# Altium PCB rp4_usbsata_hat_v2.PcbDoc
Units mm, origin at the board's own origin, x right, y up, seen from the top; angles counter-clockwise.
Board outline 100 x 100 mm, 4 copper layers (Top Layer, Int1 (GND), Int2 (PWR), Bottom Layer), stack 1.369 mm thick; 67 components, 71 nets, 344 pads, 194 vias.
Unrouted connection lines stored in the file: 33.
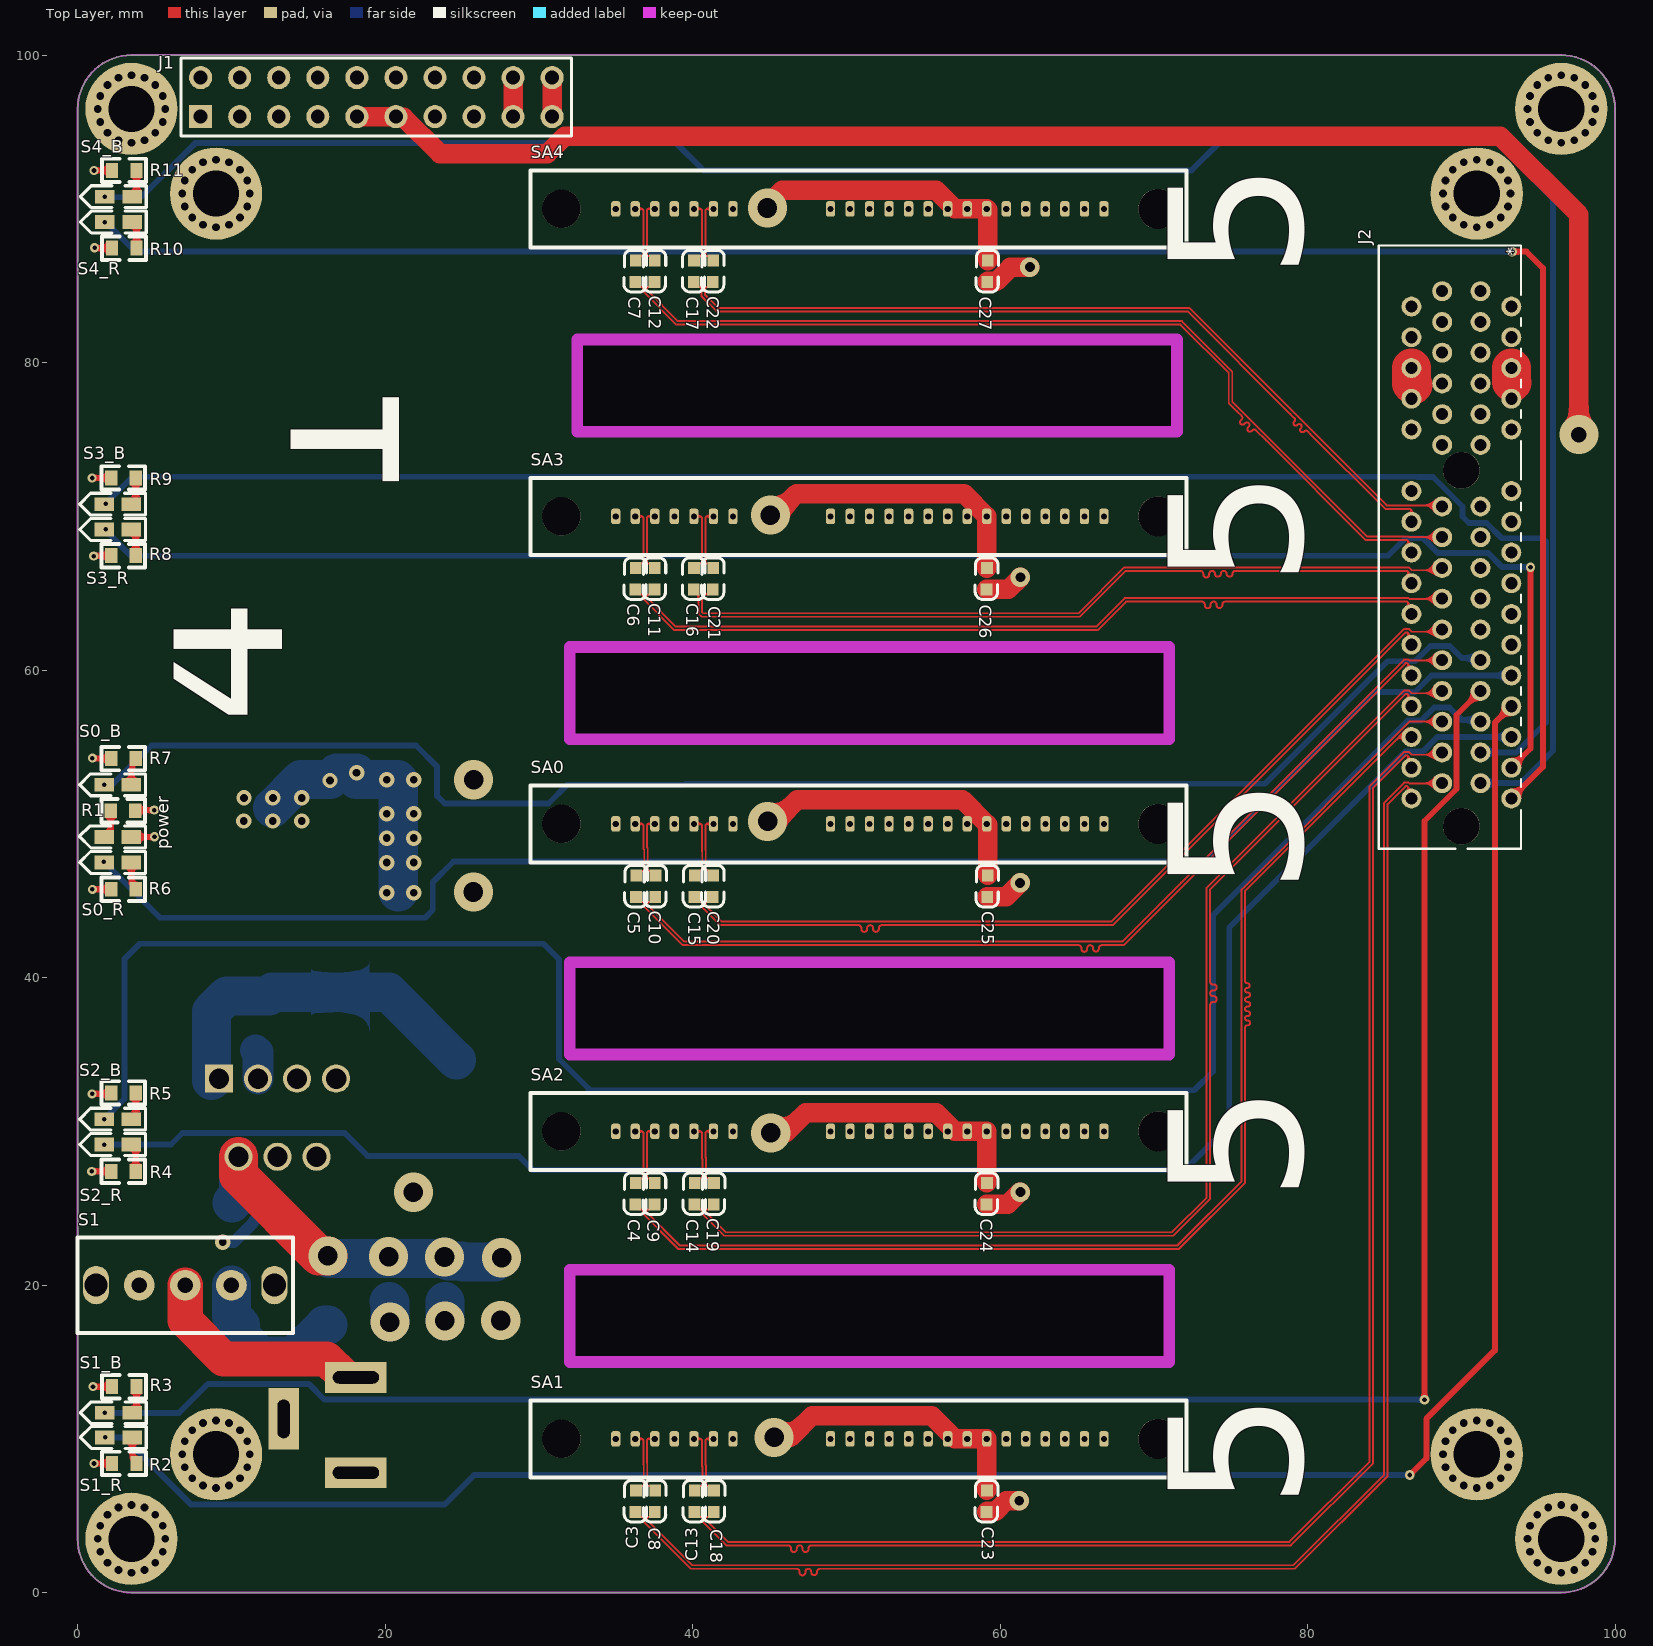
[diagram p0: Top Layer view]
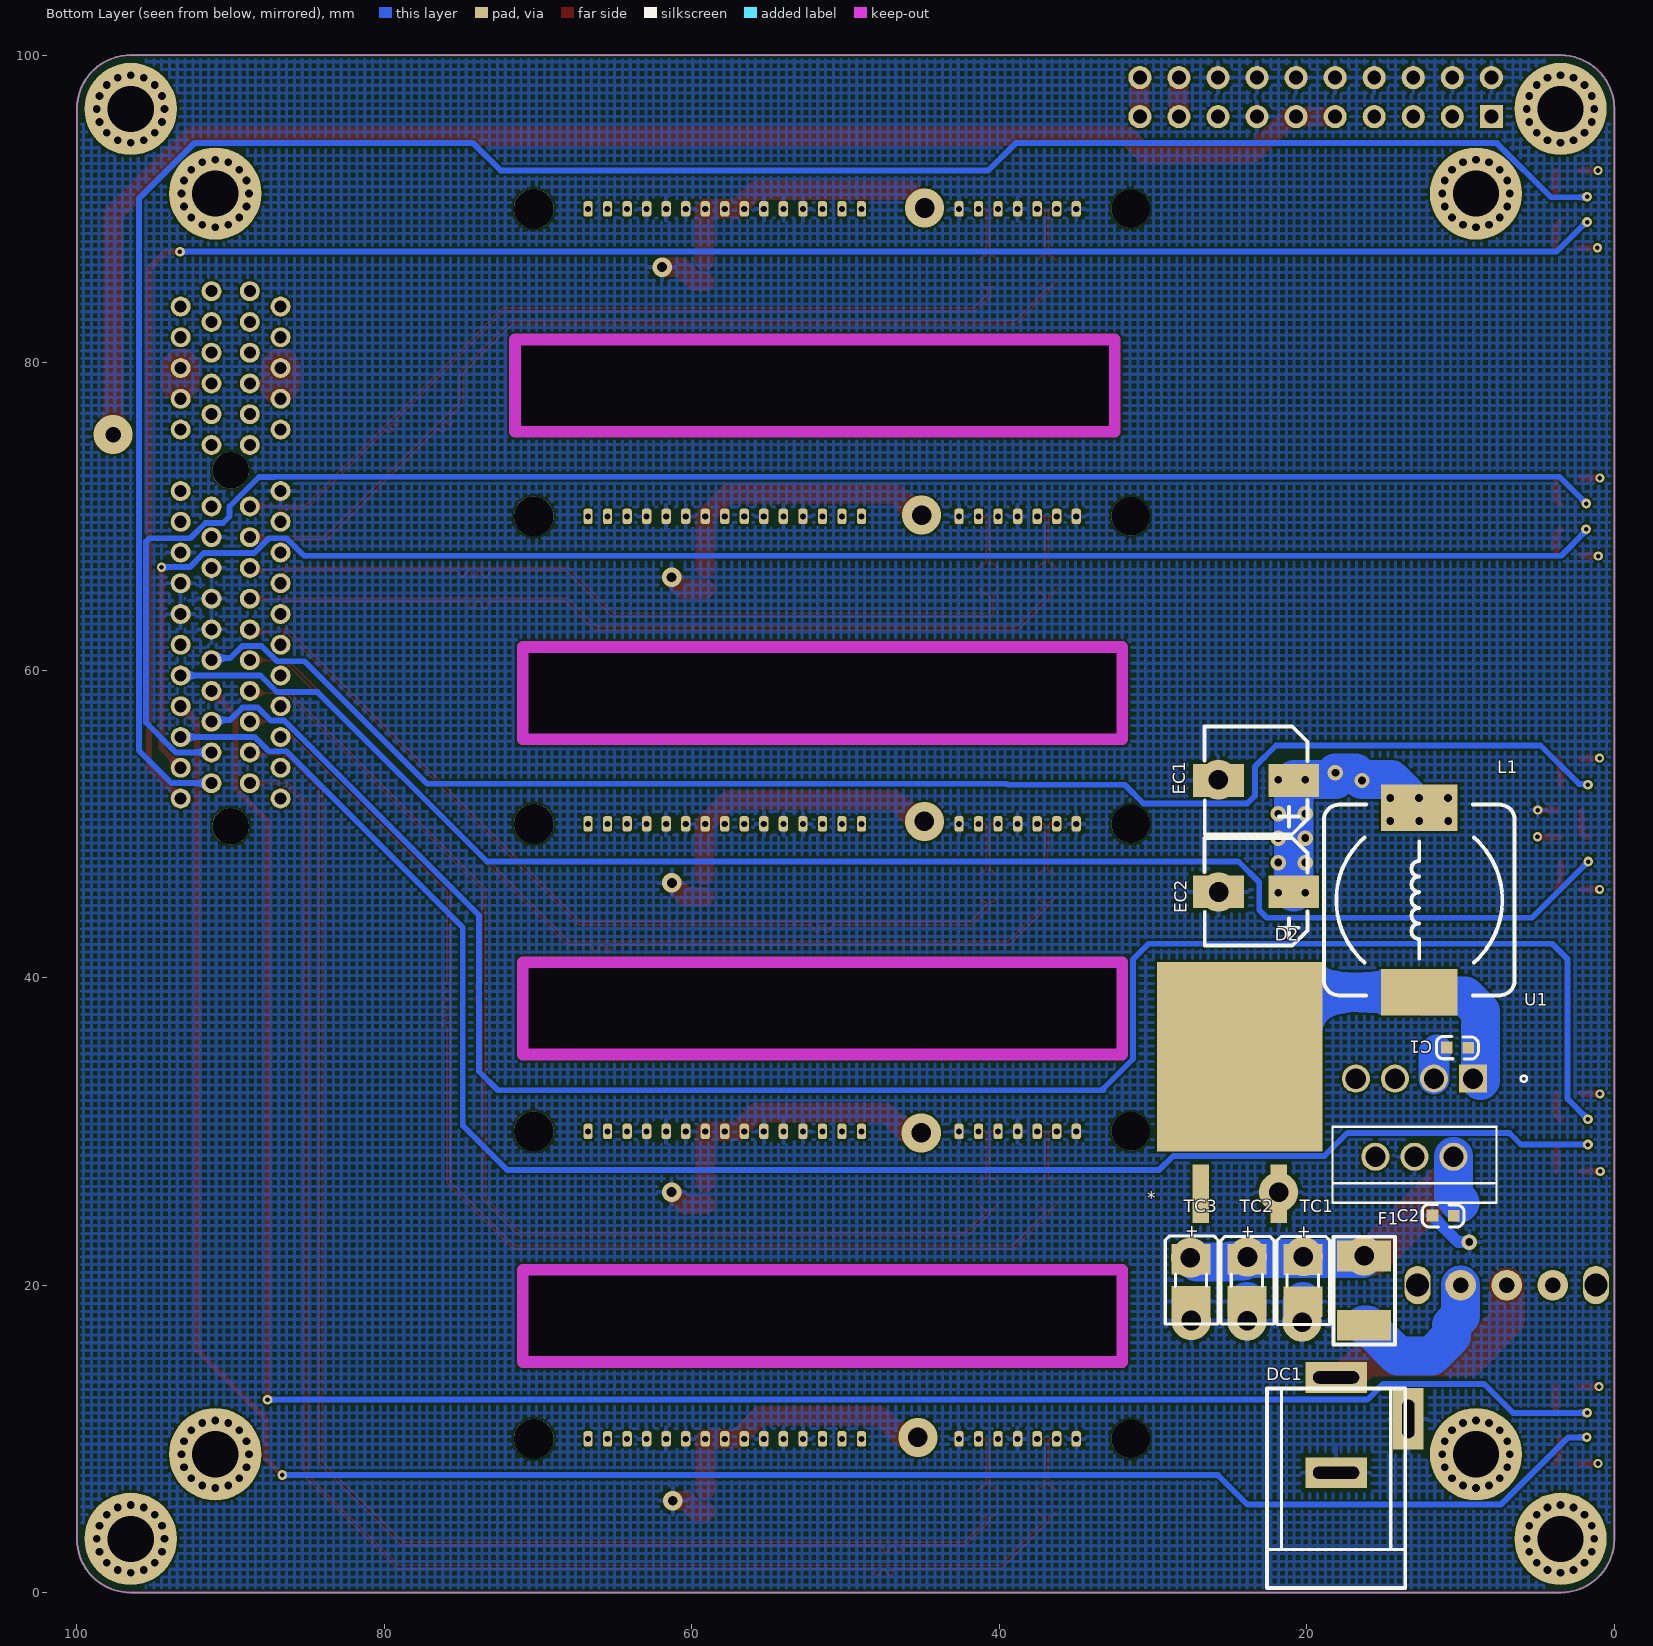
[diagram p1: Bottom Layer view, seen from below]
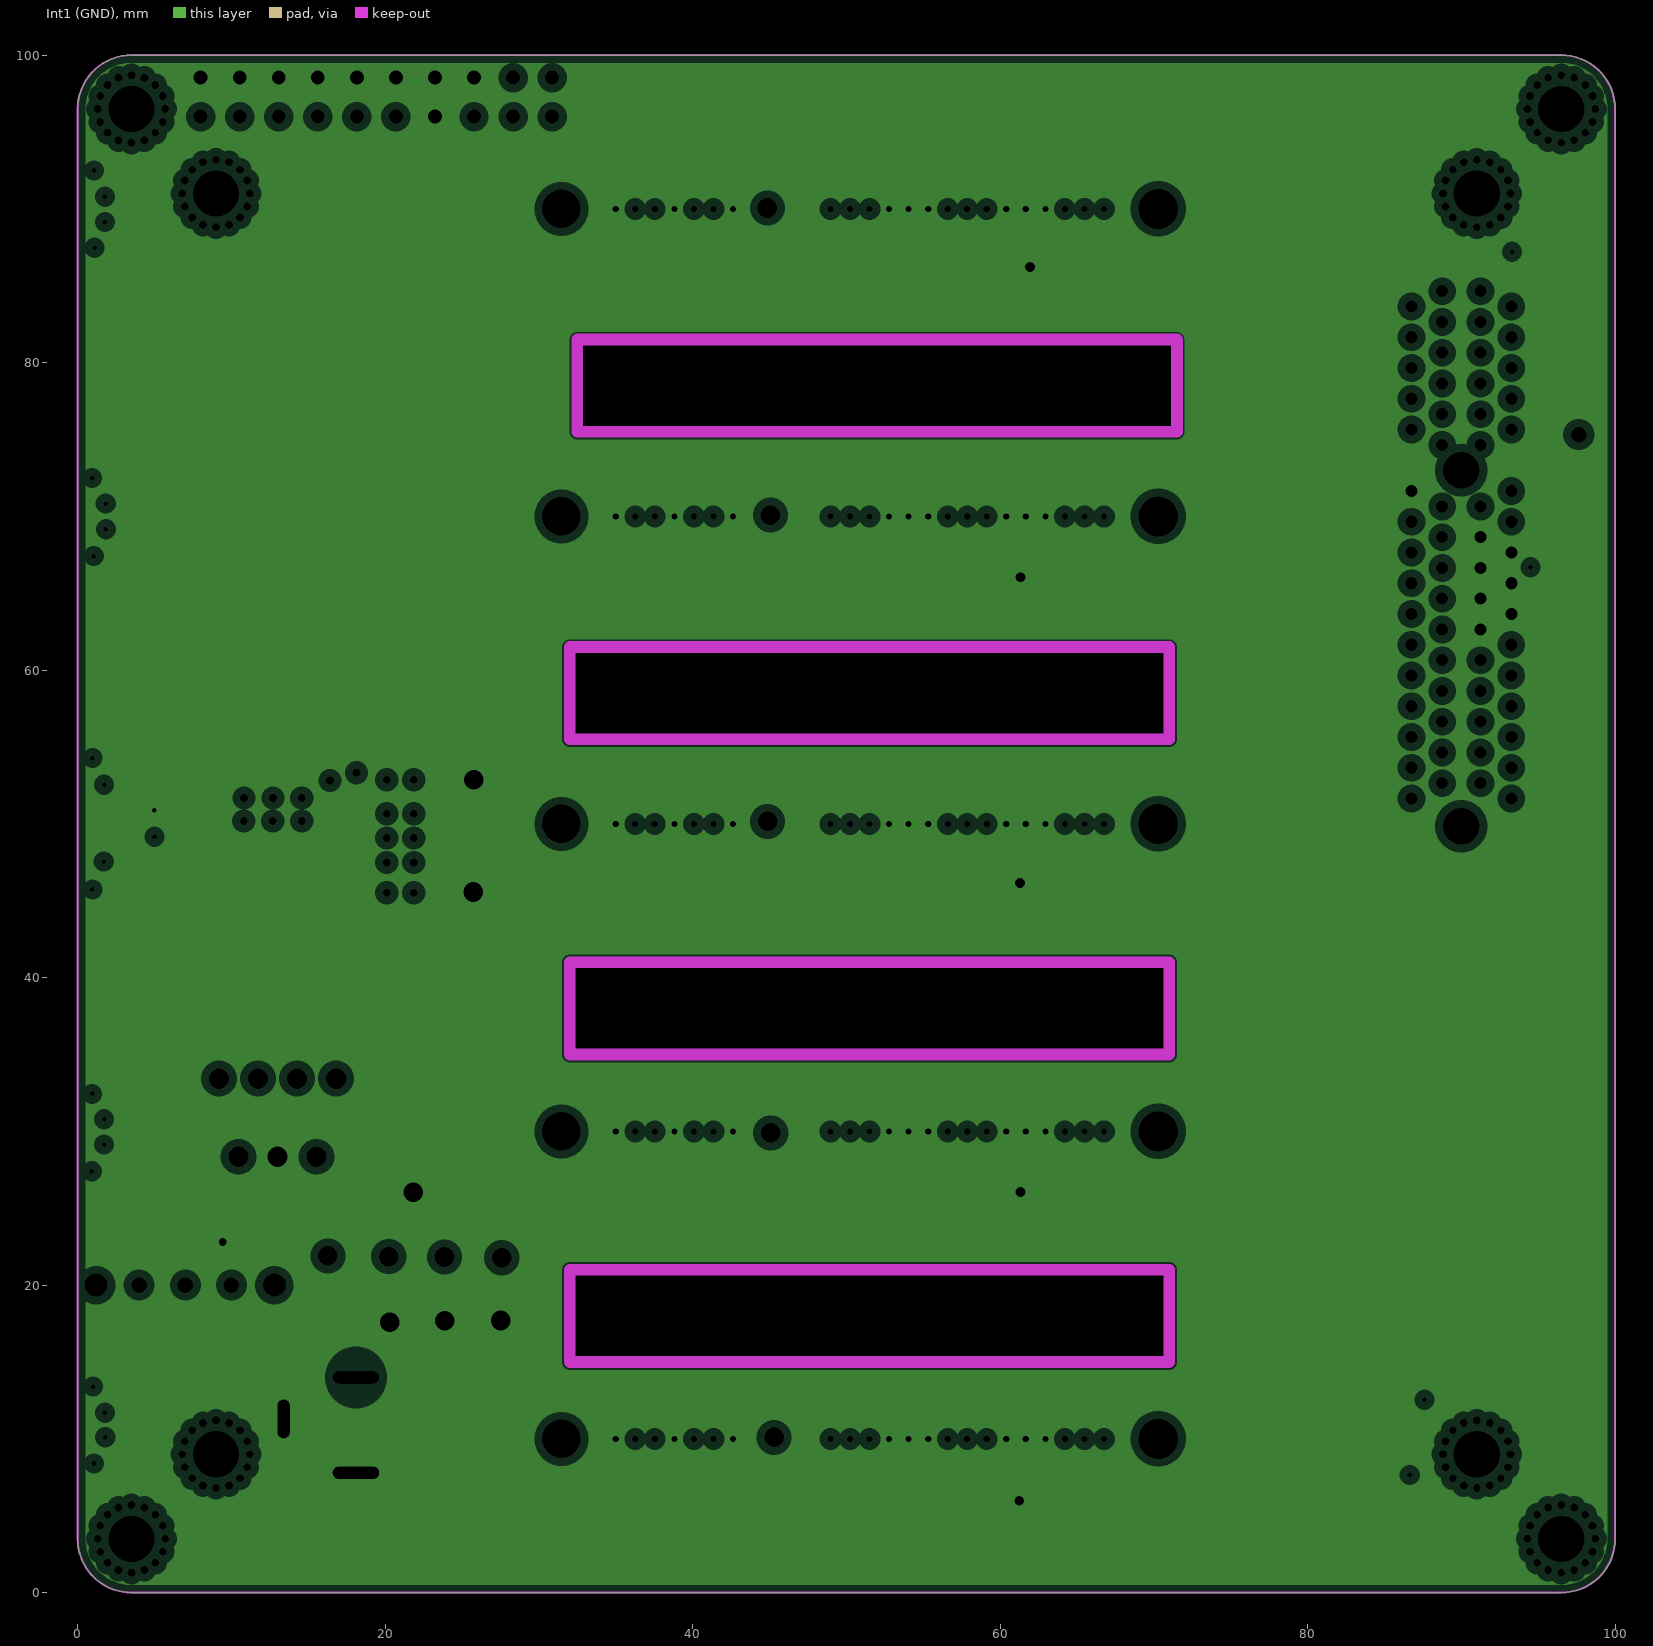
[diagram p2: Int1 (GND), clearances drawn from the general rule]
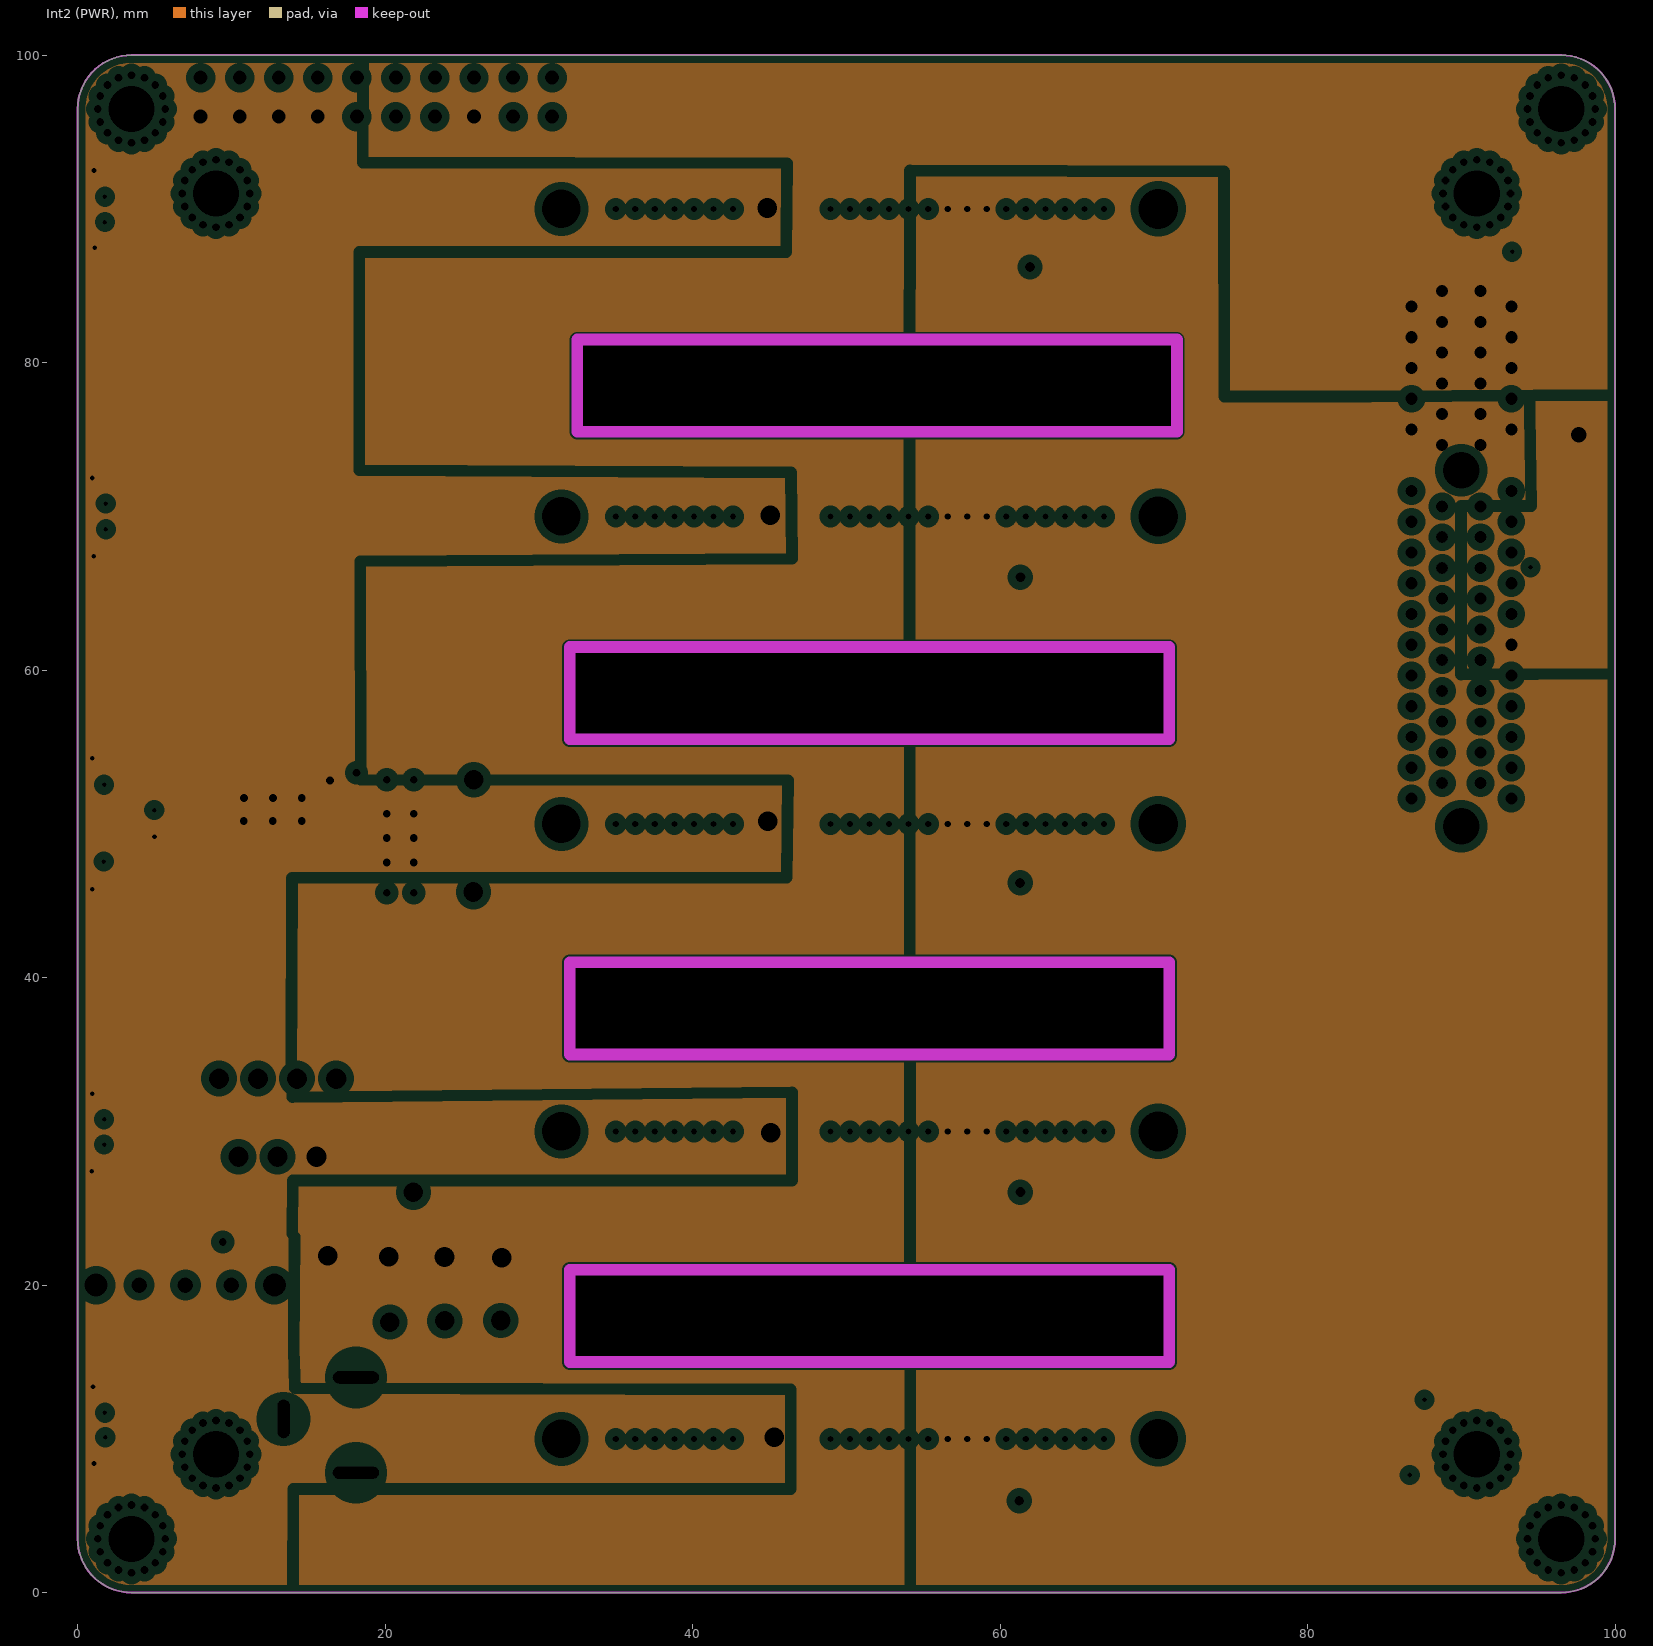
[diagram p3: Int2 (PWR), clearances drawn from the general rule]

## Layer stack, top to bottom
Top Solder: solder mask 0.0254, SM-001, Dk 4
Top Layer: signal copper 0.035
Dielectric 1: prepreg 0.1295, PP-017, Dk 4.3
Dielectric 2: prepreg 0.1295, PP-017, Dk 4.3
Int1 (GND): plane copper 0.035, net GND
Dielectric 3: core 0.7112, Core-039, Dk 4.8
Int2 (PWR): plane copper 0.035, net (Multiple Nets)
Dielectric 4: prepreg 0.1295, PP-017, Dk 4.3
Dielectric 5: prepreg 0.1295, PP-017, Dk 4.3
Bottom Layer: signal copper 0.035
Bottom Solder: solder mask 0.0254, SM-001, Dk 4

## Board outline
0,3.5 0,96.5 cw(c3.5,96.5) 3.5,100 96.5,100 cw(c96.5,96.5) 100,96.5 100,3.5 cw(c96.5,3.5) 96.5,0 3.5,0 cw(c3.5,3.5)
cut-out: 32,55.5 32,61.5 71,61.5 71,55.5
cut-out: 32.5,75.5 71.5,75.5 71.5,81.5 32.5,81.5
cut-out: 32,15 71,15 71,21 32,21
cut-out: 32,35 71,35 71,41 32,41

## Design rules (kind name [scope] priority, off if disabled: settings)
Clearance [All] p1: gap=0.127 ignorepadtopadclearanceinfootprint=FALSE
Clearance Clearance_1 [All] p2: gap=0.089 ignorepadtopadclearanceinfootprint=FALSE
DiffPairsRouting DiffPair_SATA_CDiffPairsRouting [InDifferentialPair ('NewDifferentialPair2') Or InDifferentialPair ('NewDifferentialPair1') Or InDifferentialPair ('NewDifferentialPair5') Or InDifferentialPair ('NewDifferentialPair6') Or InDifferentialPair ('NewDifferentialPair8') Or InDifferentialPair ('NewDifferentialPair9') Or InDifferentialPair ('NewDifferentialPair10') Or InDifferentialPair ('NewDifferentialPair4') Or InDifferentialPair ('NewDifferentialPair3') Or InDifferentialPair ('NewDifferentialPair7')] p1: maxlimit=0.102 minlimit=0.102 mostfreqgap=0.102 toplayer_minwidth=0.126 toplayer_maxwidth=0.126 toplayer_prefwidth=0.126 bottomlayer_minwidth=0.126 bottomlayer_maxwidth=0.126 bottomlayer_prefwidth=0.126 maxuncoupledlength=12.7
DiffPairsRouting DiffPair_SATADiffPairsRouting [InDifferentialPair ('RX1') Or InDifferentialPair ('RX3') Or InDifferentialPair ('TX2') Or InDifferentialPair ('TX3') Or InDifferentialPair ('RX4') Or InDifferentialPair ('TX1') Or InDifferentialPair ('TX4') Or InDifferentialPair ('RX2')] p2: maxlimit=0.102 minlimit=0.102 mostfreqgap=0.102 toplayer_minwidth=0.126 toplayer_maxwidth=0.126 toplayer_prefwidth=0.126 bottomlayer_minwidth=0.126 bottomlayer_maxwidth=0.126 bottomlayer_prefwidth=0.126 maxuncoupledlength=12.7
DiffPairsRouting DiffPair_SATA0DiffPairsRouting [InDifferentialPair ('TX0') Or InDifferentialPair ('RX0')] p3: maxlimit=0.102 minlimit=0.102 mostfreqgap=0.102 toplayer_minwidth=0.126 toplayer_maxwidth=0.126 toplayer_prefwidth=0.126 bottomlayer_minwidth=0.126 bottomlayer_maxwidth=0.126 bottomlayer_prefwidth=0.126 maxuncoupledlength=12.7
DiffPairsRouting [All] p4: maxlimit=0.254 minlimit=0.254 mostfreqgap=0.254 toplayer_minwidth=0.381 toplayer_maxwidth=0.381 toplayer_prefwidth=0.381 bottomlayer_minwidth=0.381 bottomlayer_maxwidth=0.381 bottomlayer_prefwidth=0.381 maxuncoupledlength=12.7
HoleSize [All] p1: absolutevalues=TRUE maxlimit=10 minlimit=0.025 maxpercent=80.000 minpercent=20.000
HoleToHoleClearance [All] p1: gap=0.127 allowstackedmicrovias=TRUE
MatchedLengths DiffPair_SATA_CMatchedLengths [InDifferentialPair ('NewDifferentialPair2') Or InDifferentialPair ('NewDifferentialPair1') Or InDifferentialPair ('NewDifferentialPair5') Or InDifferentialPair ('NewDifferentialPair6') Or InDifferentialPair ('NewDifferentialPair8') Or InDifferentialPair ('NewDifferentialPair9') Or InDifferentialPair ('NewDifferentialPair10') Or InDifferentialPair ('NewDifferentialPair4') Or InDifferentialPair ('NewDifferentialPair3') Or InDifferentialPair ('NewDifferentialPair7')] p1: tolerance=0.076 checknetsindiffpair=TRUE checkdiffpairvsdiffpair=FALSE checkxsignals=FALSE checkothers=FALSE
MatchedLengths DiffPair_SATAMatchedLengths [InDifferentialPair ('RX1') Or InDifferentialPair ('RX3') Or InDifferentialPair ('TX2') Or InDifferentialPair ('TX3') Or InDifferentialPair ('RX4') Or InDifferentialPair ('TX1') Or InDifferentialPair ('TX4') Or InDifferentialPair ('RX2')] p2: tolerance=0.076 checknetsindiffpair=TRUE checkdiffpairvsdiffpair=FALSE checkxsignals=FALSE checkothers=FALSE
MatchedLengths DiffPair_SATA0MatchedLengths [InDifferentialPair ('TX0') Or InDifferentialPair ('RX0')] p3: tolerance=0.076 checknetsindiffpair=TRUE checkdiffpairvsdiffpair=FALSE checkxsignals=FALSE checkothers=FALSE
MinimumSolderMaskSliver [All] p1: minsoldermaskwidth=0.126
PlaneClearance [All] p1: clearance=0.508
PlaneConnect [All] p1: planeconnectstyle=Relief reliefexpansion=0.508 reliefentries=4 reliefconductorwidth=0.254 reliefairgap=0.254
PolygonConnect [All] p1: connectstyle=Relief reliefconductorwidth=0.254 reliefentries=4 polygonreliefangle="90 Angle" airgapwidth=0.254
RoutingVias [All] p1: holewidth=0.3 width=0.6 viastyle="Through Hole" minholewidth=0.3 minwidth=0.6 maxholewidth=5 maxwidth=10
SilkToSilkClearance [All] p1 off: silktosilkclearance=0.254
SilkToSolderMaskClearance [IsPad] p1 off: minsilkscreentomaskgap=0.254 clearancetoexposedcopper=TRUE
SolderMaskExpansion [All] p1: expansion=0.102 istentingtop=FALSE
Width [All] p1: maxlimit=5.08 minlimit=0.254 preferedwidth=0.254
22 further rules are at their usual default settings.

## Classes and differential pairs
differential pair NewDifferentialPair10: +NetC7_1 -NetC12_1
differential pair NewDifferentialPair9: +NetC22_1 -NetC17_1
differential pair NewDifferentialPair8: +NetC21_1 -NetC16_1
differential pair NewDifferentialPair7: +NetC6_1 -NetC11_1
differential pair NewDifferentialPair6: +NetC5_1 -NetC10_1
differential pair NewDifferentialPair5: +NetC20_1 -NetC15_1
differential pair NewDifferentialPair4: +NetC4_1 -NetC9_1
differential pair NewDifferentialPair3: +NetC19_1 -NetC14_1
differential pair NewDifferentialPair2: +NetC18_1 -NetC13_1
differential pair NewDifferentialPair1: +NetC3_1 -NetC8_1
differential pair TX4: +TX4_P -TX4_N
differential pair TX3: +TX3_P -TX3_N
differential pair TX2: +TX2_P -TX2_N
differential pair TX1: +TX1_P -TX1_N
differential pair TX0: +TX0_P -TX0_N
differential pair RX4: +RX4_P -RX4_N
differential pair RX3: +RX3_P -RX3_N
differential pair RX2: +RX2_P -RX2_N
differential pair RX1: +RX1_P -RX1_N
differential pair RX0: +RX0_P -RX0_N

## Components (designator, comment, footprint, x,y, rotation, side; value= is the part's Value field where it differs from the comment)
C1 "0.01uF" 0603C 10.91,35.47 r180 bottom
C2 "0.47uF" 0603C 11.84,24.54 r180 bottom
C3 "10nF" 0603C 36.32,6.65 r270 top
C4 "10nF" 0603C 36.3,26.65 r270 top
C5 "10nF" 0603C 36.35,46.65 r270 top
C6 "10nF" 0603C 36.3,66.65 r270 top
C7 "10nF" 0603C 36.3,86.65 r270 top
C8 "10nF" 0603C 37.57,6.65 r270 top
C9 "10nF" 0603C 37.55,26.65 r270 top
C10 "10nF" 0603C 37.6,46.65 r270 top
C11 "10nF" 0603C 37.55,66.65 r270 top
C12 "10nF" 0603C 37.55,86.65 r270 top
C13 "10nF" 0603C 40.15,6.65 r270 top
C14 "10nF" 0603C 40.15,26.65 r270 top
C15 "10nF" 0603C 40.15,46.65 r270 top
C16 "10nF" 0603C 40.1,66.65 r270 top
C17 "10nF" 0603C 40.1,86.65 r270 top
C18 "10nF" 0603C 41.4,6.65 r270 top
C19 "10nF" 0603C 41.4,26.65 r270 top
C20 "10nF" 0603C 41.35,46.65 r270 top
C21 "10nF" 0603C 41.35,66.65 r270 top
C22 "10nF" 0603C 41.35,86.65 r270 top
C23 "4.7uF" 0603C 59.15,6.65 r270 top
C24 "4.7uF" 0603C 59.15,26.65 r270 top
C25 "4.7uF" 0603C 59.2,46.65 r270 top
C26 "4.7uF" 0603C 59.15,66.65 r270 top
C27 "4.7uF" 0603C 59.2,86.65 r270 top
D2 "VS-6TQ045SPBF" TO-263-2 24.362,30.4 r180 bottom
DC1 "DC_12V" DC-005 18.1,14 r270 bottom
EC1 "180uF/16V" SMD-EC6.3X6.3X10 20.83,52.83 r0 bottom
EC2 "180uF/16V" SMD-EC6.3X6.3X10 20.83,45.58 r0 bottom
F1 "16V 3A" FUSE-1812 16.28,17.397 r90 bottom
J1 "Power" "Pin HDR2X10/2.54mm-S" 8,96 r0 top
J2 "PCIEX4-64P" PCIEX4-64P 90,73 r270 top
L1 "22uH" CDRH124 12.687,45.05 r90 bottom
power "LED" LED-0603G 3.5,49.15 r180 top
R1 "1K" 0603R 3.75,50.85 r180 top
R2 "330" 0603R 2.229,8.4 r0 top
R3 "330" 0603R 2.229,13.4 r0 top
R4 "330" 0603R 2.179,27.4 r0 top
R5 "330" 0603R 2.179,32.5 r0 top
R6 "330" 0603R 2.179,45.75 r0 top
R7 "330" 0603R 2.179,54.25 r0 top
R8 "330" 0603R 2.179,67.45 r0 top
R9 "330" 0603R 2.179,72.5 r0 top
R10 "330" 0603R 2.229,87.45 r0 top
R11 "330" 0603R 2.229,92.5 r0 top
S0_B "LED" LED-0603W 3.5,52.55 r180 top
S0_R "LED" LED-0603W 3.5,47.5 r180 top
S1 "SW_ALL" SS-12D10 10,20 r180 top
S1_B "LED" LED-0603W 3.55,11.7 r180 top
S1_R "LED" LED-0603W 3.55,10.1 r180 top
S2_B "LED" LED-0603W 3.5,30.8 r180 top
S2_R "LED" LED-0603W 3.5,29.15 r180 top
S3_B "LED" LED-0603W 3.5,70.8 r180 top
S3_R "LED" LED-0603W 3.5,69.15 r180 top
S4_B "LED" LED-0603W 3.55,90.8 r180 top
S4_R "LED" LED-0603W 3.55,89.15 r180 top
SA0 "SATA Connector" "SATA Female" 35,50 r0 top
SA1 "SATA Connector" "SATA Female" 35,10 r0 top
SA2 "SATA Connector" "SATA Female" 35,30 r0 top
SA3 "SATA Connector" "SATA Female" 35,70 r0 top
SA4 "SATA Connector" "SATA Female" 35,90 r0 top
TC1 "15uF/16V" TAJ-B/3528 20.16,20.37 r270 bottom
TC2 "15uF/16V" TAJ-B/3528 23.8,20.38 r270 bottom
TC3 "15uF/16V" TAJ-B/3528 27.43,20.39 r270 bottom
U1 "Part Number: LM2678T-5.0/NOPB" TA07Bm_TEX 9.19,33.431 r0 bottom value=Value

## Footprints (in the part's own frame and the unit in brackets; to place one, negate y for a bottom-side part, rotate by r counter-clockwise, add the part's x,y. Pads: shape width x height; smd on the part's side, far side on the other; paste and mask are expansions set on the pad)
0603C [mil]
  rect 30x30 smd: 1(0.21,-0.35) 2(55.21,-1.35)
  silkscreen extent -26,-30 81,28, body extent -1,-15 62,16, height 12
0603R [mm]
  rect 0.8x0.965 smd: 1(0,0) 2(1.6,0)
  silkscreen extent -0.63,-0.76 2.21,0.76, body extent -0.04,-0.41 1.56,0.41, height 0.45
CDRH124 [mm] "12*12*4.5mm（长宽高）"
  rect 3x5 smd: 1(-6,0) 2(6,0)
  silkscreen extent -6.2,-6.2 6.2,6.2, body extent -5.87,-6.03 6.13,5.97, height 4.55
DC-005 [mm] "5.5X2.1mm"
  rect 2x4 hole 0.8 slot 3 at 90 deg: 1(0,0) 2(6.2,0)
  rect 4x2 hole 0.8 slot 2.5 at 0 deg: 3(2.7,4.7)
  silkscreen extent 0.72,-4.5 13.7,4.5, body extent -0.4,-4.52 13.65,4.78, height 11.2
FUSE-1812 [mm]
  rect 2x3.5 smd: 1(0,0) 2(4.5,0)
  silkscreen extent -1.25,-2 5.75,2, body extent -0.16,-1.61 4.66,1.61, height 1.32
LED-0603G [mil]
  rect 50x35 smd: A(0,0.26) K(70,0.26)
  silkscreen extent -36,-28 134,28, body extent 4,-15 66,17, height 24
LED-0603W [mil]
  rect 50x35 smd: A(0,0.26) K(70,0.26)
  silkscreen extent -36,-28 133,28, body extent 4,-15 66,17, height 24
PCIEX4-64P [mil]
  round 94 hole 94: 65(0,0) 66(911.42,0)
  round 51 hole 31 mask+0: A1(-458.66,49.21) A2(-419.29,127.95) A3(-379.92,49.21) A4(-340.55,127.95) A5(-301.18,49.21) A6(-261.81,127.95) A7(-222.44,49.21) A8(-183.07,127.95) A9(-143.7,49.21) A10(-104.33,127.95) A11(-64.96,49.21) A12(53.15,127.95) A13(92.52,49.21) A14(131.89,127.95) A15(171.26,49.21) A16(210.63,127.95) A17(250,49.21) A18(289.37,127.95) A19(328.74,49.21) A20(368.11,127.95) A21(407.48,49.21) A22(446.85,127.95) A23(486.22,49.21) A24(525.59,127.95) A25(564.96,49.21) A26(604.33,127.95) A27(643.7,49.21) A28(683.07,127.95) A29(722.44,49.21) A30(761.81,127.95) A31(801.18,49.21) A32(840.55,127.95) B1(-458.66,-49.21) B2(-419.29,-127.95) B3(-379.92,-49.21) B4(-340.55,-127.95) B5(-301.18,-49.21) B6(-261.81,-127.95) B7(-222.44,-49.21) B8(-183.07,-127.95) B9(-143.7,-49.21) B10(-104.33,-127.95) B11(-64.96,-49.21) B12(53.15,-127.95) B13(92.52,-49.21) B14(131.89,-127.95) B15(171.26,-49.21) B16(210.63,-127.95) B17(250,-49.21) B18(289.37,-127.95) B19(328.74,-49.21) B20(368.11,-127.95) B21(407.48,-49.21) B22(446.85,-127.95) B23(486.22,-49.21) B24(525.59,-127.95) B25(564.96,-49.21) B26(604.33,-127.95) B27(643.7,-49.21) B28(683.07,-127.95) B29(722.44,-49.21) B30(761.81,-127.95) B31(801.18,-49.21) B32(840.55,-127.95)
  silkscreen extent -576,-211 969,153, body extent -459,49 -449,59, height 10
"Pin HDR2X10/2.54mm-S" [mm] "Connector; Header; 10x2 Position"
  rect 1.5x1.5 hole 0.9: 1(0,0)
  round 1.5 hole 0.9: 2(0,2.54) 3(2.54,0) 4(2.54,2.54) 5(5.08,0) 6(5.08,2.54) 7(7.62,0) 8(7.62,2.54) 9(10.16,0) 10(10.16,2.54) 11(12.7,0) 12(12.7,2.54) 13(15.24,0) 14(15.24,2.54) 15(17.78,0) 16(17.78,2.54) 17(20.32,0) 18(20.32,2.54) 19(22.86,0) 20(22.86,2.54)
  silkscreen extent -1.27,-1.27 24.13,3.81, body extent -1.27,-1.27 24.13,3.81, height 7.58
"SATA Female" [mm] "1.27mm Pitch Serial ATA Backplane Receptacle, Through Hole, Vertical, Extended Height, 0.76μm Gold (Au) Selective, 22 Circuits, Lead-Free"
  round 2.5 hole 2.5: 0(-3.535,0)
  round 2.6 hole 2.6: 0(35.285,0)
  rrect50% 0.6x1 hole 0.4: 1(0,0) 2(1.27,0) 3(2.54,0) 4(3.81,0) 5(5.08,0) 6(6.35,0) 7(7.62,0) 8(13.97,0) 9(15.24,0) 10(16.51,0) 11(17.78,0) 12(19.05,0) 13(20.32,0) 14(21.59,0) 15(22.86,0) 16(24.13,0) 17(25.4,0) 18(26.67,0) 19(27.94,0) 20(29.21,0) 21(30.48,0) 22(31.75,0)
  silkscreen extent -5.55,-2.5 37.13,2.5, body extent -5.54,-2.5 37.19,2.5, height 15.85
SMD-EC6.3X6.3X10 [mm]
  rect 3.3x2.132 smd: 1(0.021,0) 2(4.921,0)
  silkscreen extent -0.88,-3.5 5.84,3.5, body extent -1.09,-3.3 5.91,3.3, height 5.4
SS-12D10 [mm]
  oval 1.7x2.5 hole 1.5: 0(-2.794,0) 0(8.8,0)
  round 2 hole 1: 1(0,0) 2(3,0) 3(6,0)
  silkscreen extent -4,-3.1 10,3.1, body extent -3.95,-3.15 10.05,3.05, height 9.65
TA07Bm_TEX [mil]
  rect 72x72 hole 52: 1(0,0)
  round 72 hole 52 mask+0: 2(50,200) 3(100,0) 4(150,200) 5(200,0) 6(250,200) 7(300,0)
  silkscreen extent -138,-8 360,318, body extent -55,-41 355,293, height 823
TAJ-B/3528 [mil]
  rect 78.74x100 smd: 1(-51.15,-4) 2(57,-4)
  silkscreen extent -110,-70 115,65, body extent -64,-60 74,50, height 75
TO-263-2 [mil]
  rect 43x150 smd paste+0 mask+0: 1(-100,-175.5) 3(100,-175.5)
  rect 424x486 smd paste+0 mask+0: 2(0,175.5)
  body extent -210,-149 210,399, height 190

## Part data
C1 C2 C3 C4 C5 C6 C7 C8 C9 C10 C11 C12 C13 C14 C15 C16 C17 C18 C19 C20 C21 C22 C23 C24 C25 C26 C27: library part CAP, "无极性电容"
D2: "直流反向耐压（Vr）：45V 平均整流电流（Io）：6A 正向"
DC1: library part DC_Socket
EC1 EC2: library part SMD_ECAP, "贴片电解电容"
F1: library part FUSE
J1: library part "Pin HDR2X10"
J2: "No Description Available", Manufacturer_Part_Number=87715-9106
L1: library part INDUCTOR, "INDUCTOR"
R1 R2 R3 R4 R5 R6 R7 R8 R9 R10 R11: library part RES
S1: library part SS-12D10
SA0 SA1 SA2 SA3 SA4: library part SATA_Female_22P
TC1 TC2 TC3: library part TCAP, "钽电容"
U1: library part LM2678T-5.0/NOPB, "No Description Available"

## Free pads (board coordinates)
  round 6 hole 3: 0(3.5,96.5) 0(3.5,3.5) 0(9,9) 0(9,91) 0(91,9) 0(91,91) 0(96.5,3.5) 0(96.5,96.5)

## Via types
v1: diameter 1, hole 0.5, Top Layer to Bottom Layer, 147 vias
v2: diameter 2.54, hole 1.27, Top Layer to Bottom Layer, 15 vias
v3: diameter 0.6, hole 0.3, Top Layer to Bottom Layer, 13 vias
v4: diameter 0.635, hole 0.3, Top Layer to Bottom Layer, 13 vias
v5: diameter 1.27, hole 0.635, Top Layer to Bottom Layer, 5 vias
v6: diameter 2.54, hole 1.016, Top Layer to Bottom Layer, 1 vias

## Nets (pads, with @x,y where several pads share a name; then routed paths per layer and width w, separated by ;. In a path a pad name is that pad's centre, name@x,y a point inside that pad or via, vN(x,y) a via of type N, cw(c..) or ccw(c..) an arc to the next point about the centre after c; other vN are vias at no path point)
5.0V: C23.1 C24.1 C25.1 C26.1 C27.1 EC1.1 EC2.1 J1.1 J1.3 J1.5 J1.7 J2.A9 J2.A10 J2.A11 J2.B9 J2.B10 J2.B11 L1.2 power.A R2.1 R3.1 R4.1 R5.1 R6.1 R7.1 R8.1 R9.1 R10.1 R11.1 SA0.14 SA0.15 SA0.16 SA1.14 SA1.15 SA1.16 SA2.14 SA2.15 SA2.16 SA3.14 SA3.15 SA3.16 SA4.14 SA4.15 SA4.16 U1.6 | length 123.1
  Top Layer w0.381: v3(0.92,27.4) R4.1 ; v3(0.94,32.44) 2.119,32.44 R5.1 ; v3(0.94,72.5) R9.1 ; v3(0.96,45.74) 0.97,45.75 R6.1 ; v3(0.96,54.28) 1.02,54.28 1.05,54.25 R7.1 ; v3(1,13.4) R3.1 ; v3(1.04,67.42) 1.07,67.45 R8.1 ; v3(1.06,8.4) R2.1 ; v3(1.06,92.5) R11.1 ; v3(1.1,87.48) 1.13,87.45 R10.1 ; power.A 4.984,49.144 v3(5,49.16)
  Top Layer w1.27: v2(44.86,90.06) 44.86,90.24 45.844,91.224 55.832,91.224 57.056,90 SA4.15 SA4.16 59.191,89.939 C27.1 ; v2(44.88,50.16) 45.4,50.16 46.82,51.58 57.55,51.58 SA0.16 59.191,49.939 C25.1 ; v2(45.06,70.08) 45.36,70.08 46.76,71.48 57.65,71.48 SA3.16 59.141,69.989 C26.1 ; v2(45.08,29.9) 46.04,29.9 47.364,31.224 55.832,31.224 57.056,30 SA2.15 SA2.16 59.13,26.655 C24.1 ; v2(45.3,10.1) 46.36,10.1 47.78,11.52 55.536,11.52 57.056,10 SA1.15 SA1.16 59.141,9.989 C23.1
  Bottom Layer w2.54: L1.2 14.517,52.88 16.41,52.88 16.853,53.323 v1(18.142,53.323) ; v1@18.142,52.88 20.801,52.88 EC1.1 20.851,50.665 20.851,49.2 20.851,47.585 EC2.1
  other v1: 20.1,45.525 21.86,45.53 20.1,47.485 21.86,47.485 20.1,49.078 21.86,49.078 10.81,50.19 12.69,50.19 14.57,50.19 20.1,50.67 21.86,50.67 10.82,51.69 12.7,51.69 14.58,51.69 16.41,52.82 20.1,52.875 21.86,52.88
FAN_PWM: J1.19 J1.20 | length 2.5
  Top Layer w1.27: J1.19 J1.20
FAN_RPM: J1.17 J1.18 | length 2.5
  Top Layer w1.27: J1.17 J1.18
GND: C2.1 C23.2 C24.2 C25.2 C26.2 C27.2 D2.3 DC1.2 DC1.3 EC1.2 EC2.2 J1.2 J1.4 J1.6 J1.8 J1.10 J1.12 J1.13 J1.14 J1.16 J2.A15 J2.A16 J2.A17 J2.A18 J2.A19 J2.A20 J2.A21 J2.B12 R1.1 SA0.1 SA0.4 SA0.7 SA0.11 SA0.12 SA0.13 SA0.17 SA0.18 SA0.19 SA1.1 SA1.4 SA1.7 SA1.11 SA1.12 SA1.13 SA1.17 SA1.18 SA1.19 SA2.1 SA2.4 SA2.7 SA2.11 SA2.12 SA2.13 SA2.17 SA2.18 SA2.19 SA3.1 SA3.4 SA3.7 SA3.11 SA3.12 SA3.13 SA3.17 SA3.18 SA3.19 SA4.1 SA4.4 SA4.7 SA4.11 SA4.12 SA4.13 SA4.17 SA4.18 SA4.19 TC1.2 TC2.2 TC3.2 U1.4 | length 20.4
  Top Layer w0.381: R1.1 3.8,50.9 v3(4.98,50.9)
  Top Layer w1.27: C23.2 59.154,5.286 59.704,5.286 60.398,5.98 v5(61.24,5.98) ; C24.2 60.488,25.248 61.29,26.05 v5(61.317,26.05) ; C26.2 60.528,65.248 v5(61.32,66.04) ; C25.2 60.388,45.248 v5(61.3,46.16) ; C27.2 59.204,85.286 59.754,85.286 60.668,86.2 61.92,86.2 v5(61.94,86.22)
  Bottom Layer w0.762: v1(9.43,22.8) 10.158,22.8 11.424,24.065 11.424,24.12 C2.1
  Bottom Layer w1.524: D2.3 21.822,26.022 v2(21.84,26.04) ; v2(25.74,45.57) EC2.2 EC2.2 ; EC1.2 25.751,52.861 v2(25.76,52.87)
  Bottom Layer w2.54: TC1.2 20.31,18.874 v2(20.31,17.6) ; v2(23.88,17.67) 23.88,18.91 TC2.2
  other v2: 27.52,17.7
NetC1_1: C1.1 U1.3 | length 1.9
  Bottom Layer w2.032: 11.57,35.3 11.73,35.14 U1.3
NetC1_2: C1.2 D2.2 L1.1 U1.1 | length 23
  Bottom Layer w2.54: U1.1@8.831,33.431 8.7,33.3 8.7,35.436 8.7,37.812 9.708,38.82 12.457,38.82 L1.1 20.216,39.05 D2.2@24.633,34.634
NetC3_1: C3.1 SA1.2 | length 4.1
  Top Layer w0.126: SA1.2 36.717,10 36.791,9.926 36.791,8.357 36.822,8.326 36.822,7.021 36.748,6.947 36.614,6.947 C3.1
NetC4_1: C4.1 SA2.2 | length 4.1
  Top Layer w0.126: SA2.2 36.717,30 36.791,29.926 36.791,28.347 36.802,28.336 36.802,27.021 36.728,26.947 36.594,26.947 C4.1
NetC5_1: C5.1 SA0.2 | length 4.1
  Top Layer w0.126: SA0.2 36.717,50 36.791,49.926 36.791,48.372 36.852,48.311 36.852,47.021 36.778,46.948 36.644,46.948 C5.1
NetC6_1: C6.1 SA3.2 | length 4.1
  Top Layer w0.126: SA3.2 36.717,70 36.791,69.926 36.791,68.347 36.802,68.336 36.802,67.021 36.728,66.947 36.594,66.947 C6.1
NetC7_1: C7.1 SA4.2 | length 4.1
  Top Layer w0.126: SA4.2 36.717,90 36.791,89.926 36.791,88.347 36.802,88.336 36.802,87.021 36.728,86.948 36.594,86.948 C7.1
NetC8_1: C8.1 SA1.3 | length 4.1
  Top Layer w0.126: SA1.3 37.093,10 37.019,9.926 37.019,8.451 37.05,8.421 37.05,7.021 37.124,6.947 37.258,6.947 C8.1
NetC9_1: C9.1 SA2.3 | length 4.1
  Top Layer w0.126: SA2.3 37.093,30 37.019,29.926 37.019,28.441 37.03,28.43 37.03,27.021 37.104,26.947 37.238,26.947 C9.1
NetC10_1: C10.1 SA0.3 | length 4.1
  Top Layer w0.126: SA0.3 37.093,50 37.019,49.926 37.019,48.467 37.08,48.406 37.08,47.021 37.153,46.948 37.288,46.948 C10.1
NetC11_1: C11.1 SA3.3 | length 4.1
  Top Layer w0.126: SA3.3 37.093,70 37.019,69.926 37.019,68.442 37.03,68.43 37.03,67.021 37.104,66.947 37.238,66.947 C11.1
NetC12_1: C12.1 SA4.3 | length 4.1
  Top Layer w0.126: SA4.3 37.093,90 37.019,89.926 37.019,88.442 37.03,88.431 37.03,87.021 37.103,86.948 37.238,86.948 C12.1
NetC13_1: C13.1 SA1.5 | length 4.1
  Top Layer w0.126: SA1.5 40.527,10 40.601,9.926 40.601,8.234 40.652,8.183 40.652,7.021 40.578,6.948 40.444,6.948 C13.1
NetC14_1: C14.1 SA2.5 | length 4.1
  Top Layer w0.126: SA2.5 40.527,30 40.601,29.926 40.601,28.234 40.652,28.183 40.652,27.021 40.578,26.948 40.444,26.948 C14.1
NetC15_1: C15.1 SA0.5 | length 4.1
  Top Layer w0.126: SA0.5 40.527,50 40.601,49.926 40.601,48.221 40.627,48.196 40.627,47.036 40.553,46.963 40.459,46.963 C15.1
NetC16_1: C16.1 SA3.5 | length 4.1
  Top Layer w0.126: SA3.5 40.527,70 40.601,69.926 40.601,68.209 40.602,68.208 40.602,67.021 40.528,66.947 40.394,66.947 C16.1
NetC17_1: C17.1 SA4.5 | length 4.1
  Top Layer w0.126: SA4.5 40.527,90 40.601,89.926 40.601,88.209 ; C17.1 40.394,86.948 40.528,86.948 40.602,87.021 40.602,88.208
NetC18_1: C18.1 SA1.6 | length 4.1
  Top Layer w0.126: SA1.6 40.903,10 40.829,9.926 40.829,8.328 40.88,8.277 40.88,7.021 40.953,6.948 41.088,6.948 C18.1
NetC19_1: C19.1 SA2.6 | length 4.1
  Top Layer w0.126: SA2.6 40.903,30 40.829,29.926 40.829,28.328 40.88,28.277 40.88,27.021 40.953,26.948 41.088,26.948 C19.1
NetC20_1: C20.1 SA0.6 | length 4.1
  Top Layer w0.126: C20.1 41.023,46.963 40.928,46.963 40.855,47.036 40.855,48.29 40.829,48.316 40.829,49.926 40.903,50 SA0.6
NetC21_1: C21.1 SA3.6 | length 4.1
  Top Layer w0.126: C21.1 41.038,66.947 40.904,66.947 40.83,67.021 40.83,68.302 40.829,68.303 40.829,69.926 40.903,70 SA3.6
NetC22_1: C22.1 SA4.6 | length 4.1
  Top Layer w0.126: 40.83,88.302 40.83,87.021 40.903,86.948 41.038,86.948 C22.1 ; 40.829,88.303 40.829,89.926 40.903,90 SA4.6
NetDC1_1: DC1.1 S1.2 | length 14
  Top Layer w2.286: S1.2 7,17.7 9.5,15.2 16.186,15.2 DC1.1@17.243,14.143
NetF1_1: F1.1 S1.1 | length 10.6
  Bottom Layer w2.54: S1.1 10,18 10.585,17.415 10.585,16.685 11.879,15.391 14.064,15.391 16.07,17.397 F1.1
Netpower_K: power.K R1.2 | length 2
  Top Layer w0.381: power.K 1.896,49.144 2.15,49.398 R1.2
NetR2_2: R2.2 S1_R.A | length 1.8
  Top Layer w0.381: S1_R.A 3.55,8.762 3.829,8.483 R2.2
NetR3_2: R3.2 S1_B.A | length 1.8
  Top Layer w0.381: S1_B.A 3.575,11.694 3.829,11.948 R3.2
NetR4_2: R4.2 S2_R.A | length 1.9
  Top Layer w0.381: S2_R.A 3.525,29.144 3.779,28.89 R4.2
NetR5_2: R5.2 S2_B.A | length 1.8
  Top Layer w0.381: S2_B.A 3.525,30.794 3.779,31.048 R5.2
NetR6_2: R6.2 S0_R.A | length 1.9
  Top Layer w0.381: S0_R.A 3.5,46.112 3.779,45.833 R6.2
NetR7_2: R7.2 S0_B.A | length 1.8
  Top Layer w0.381: S0_B.A 3.5,53.56 3.57,53.629 3.57,54.041 R7.2
NetR8_2: R8.2 S3_R.A | length 1.8
  Top Layer w0.381: S3_R.A 3.525,69.144 3.779,68.89 R8.2
NetR9_2: R9.2 S3_B.A | length 1.8
  Top Layer w0.381: S3_B.A 3.525,70.794 3.779,71.048 R9.2
NetR10_2: R10.2 S4_R.A | length 1.8
  Top Layer w0.381: S4_R.A 3.575,89.144 3.829,88.89 R10.2
NetR11_2: R11.2 S4_B.A | length 1.4
  Top Layer w0.381: S4_B.A@3.829,91.073 R11.2
RX0_N: C15.2 J2.B22 | length 57.2
  Top Layer w0.126: C15.2 40.433,44.93 40.528,44.93 40.602,44.856 40.602,44.61 41.799,43.412 50.34,43.412 50.783,43.412 cw(c50.783,43.222) 50.973,43.222 50.973,43.171 ccw(c51.163,43.171) 51.353,43.171 51.353,43.222 cw(c51.543,43.222) 51.733,43.222 51.733,43.171 ccw(c51.923,43.171) 52.113,43.171 52.113,43.222 cw(c52.303,43.222) 52.303,43.412 54.06,43.412 67.329,43.412 77.838,53.922 86.374,62.458 86.479,62.458 86.553,62.384 86.553,61.847 J2.B22
RX0_P: C20.2 J2.B21 | length 57.2
  Top Layer w0.126: C20.2 40.997,44.93 40.903,44.93 40.829,44.856 40.829,44.705 41.894,43.64 67.235,43.64 77.611,54.016 86.28,62.685 86.573,62.685 86.762,62.497 88.597,62.497 J2.B21
RX1_N: C13.2 J2.B30 | length 96.4
  Top Layer w0.126: C13.2 40.433,4.93 40.553,4.93 40.627,4.856 40.627,4.635 42.189,3.072 45.76,3.072 46.203,3.072 cw(c46.203,2.882) 46.393,2.882 46.393,2.831 ccw(c46.583,2.831) 46.773,2.831 46.773,2.882 cw(c46.963,2.882) 47.153,2.882 47.153,2.831 ccw(c47.343,2.831) 47.533,2.831 47.533,2.882 cw(c47.723,2.882) 47.723,3.072 50.66,3.072 78.914,3.072 84.26,8.418 84.26,50.387 84.26,52.343 86.374,54.458 86.479,54.458 86.553,54.384 86.553,53.847 J2.B30
RX1_P: C18.2 J2.B29 | length 96.4
  Top Layer w0.126: C18.2 41.047,4.93 40.928,4.93 40.854,4.856 40.854,4.73 42.284,3.3 78.82,3.3 84.032,8.512 84.032,50.387 ; 84.032,50.453 84.032,52.437 86.28,54.685 86.573,54.685 86.762,54.497 88.597,54.497 J2.B29
RX2_N: C14.2 J2.B26 | length 75.7
  Top Layer w0.126: C14.2 40.433,24.93 40.553,24.93 40.627,24.856 40.627,24.635 42.049,23.212 71.268,23.212 73.66,25.604 73.66,37.78 73.66,38.223 cw(c73.85,38.223) 73.85,38.413 73.902,38.413 ccw(c73.902,38.603) 73.902,38.793 73.85,38.793 cw(c73.85,38.983) 73.85,39.173 73.902,39.173 ccw(c73.902,39.363) 73.902,39.553 73.85,39.553 cw(c73.85,39.743) 73.66,39.743 73.66,40.46 73.66,45.743 86.374,58.458 86.479,58.458 86.553,58.384 86.553,57.847 J2.B26
RX2_P: C19.2 J2.B25 | length 75.8
  Top Layer w0.126: C19.2 41.047,24.93 40.928,24.93 40.854,24.856 40.854,24.729 42.144,23.44 71.174,23.44 73.432,25.698 73.432,45.838 86.28,58.685 86.573,58.685 86.762,58.497 88.597,58.497 J2.B25
RX3_N: C16.2 J2.B18 | length 51.4
  Top Layer w0.126: C16.2 40.378,64.935 40.378,63.68 40.585,63.472 65.192,63.472 68.178,66.458 72.581,66.458 73.024,66.458 cw(c73.024,66.268) 73.214,66.268 73.214,66.222 ccw(c73.404,66.222) 73.594,66.222 73.594,66.268 cw(c73.784,66.268) 73.974,66.268 ccw(c74.164,66.268) 74.354,66.268 cw(c74.544,66.268) 74.734,66.268 ccw(c74.924,66.268) 75.114,66.268 cw(c75.304,66.268) 75.304,66.458 78.7,66.458 86.479,66.458 86.553,66.384 86.553,65.847 J2.B18
RX3_P: C21.2 J2.B17 | length 51.4
  Top Layer w0.126: C21.2 40.998,64.93 40.817,64.93 40.606,64.719 40.606,63.774 40.679,63.7 65.098,63.7 68.083,66.685 86.573,66.685 86.762,66.497 88.597,66.497 J2.B17
RX4_N: C17.2 J2.B14 | length 54.3
  Top Layer w0.126: C17.2@40.371,84.942 40.383,84.93 40.503,84.93 40.577,84.856 40.577,84.313 41.558,83.332 72.208,83.332 78.885,76.655 79.144,76.396 cw(c79.037,76.288) 79.144,76.181 79.126,76.162 ccw(c79.233,76.055) 79.34,75.947 79.359,75.966 cw(c79.467,75.859) 79.574,75.751 79.555,75.733 ccw(c79.663,75.625) 79.77,75.518 79.789,75.536 cw(c79.896,75.429) 80.004,75.536 80.185,75.355 85.048,70.492 86.676,70.492 86.75,70.419 J2.B14
RX4_P: C22.2 J2.B13 | length 54.5
  Top Layer w0.126: C22.2@41.156,85.089 40.997,84.93 40.878,84.93 40.804,84.856 40.804,84.408 41.652,83.56 72.302,83.56 85.142,70.72 88.68,70.72 J2.B13
S0_B: J2.A23 S0_B.K | length 97.9
  Bottom Layer w0.381: v4(1.722,52.544) 1.77,52.592 2.292,52.592 4.8,55.1 22,55.1 23.383,53.717 23.383,51.817 23.879,51.321 30.623,51.321 31.846,52.544 39.477,52.544 39.543,52.609 77.229,52.609 85.197,60.577 86.988,60.577 87.988,61.577 89.248,61.577 90.031,60.794 91.106,60.794 J2.A23
S0_R: J2.A24 S0_R.K | length 100.6
  Bottom Layer w0.381: v4(1.7,47.55) 5.35,43.9 22.6,43.9 23.1,44.4 23.1,46.2 24.45,47.55 73.33,47.55 84.357,58.577 86.988,58.577 88.061,59.65 J2.A24
S1_B: J2.A25 S1_B.K | length 134.6
  Top Layer w0.381: v4(87.6,12.55) 87.6,50.189 89.677,52.266 89.677,57.077 J2.A25
  Bottom Layer w0.381: v4(1.772,11.694) 6.59,11.694 8.476,13.579 15.025,13.579 16.055,12.55 v4(87.6,12.55)
S1_R: J2.A26 S1_R.K | length 140.2
  Top Layer w0.381: v4(86.65,7.65) 87.721,8.721 87.721,11.301 92.177,15.757 92.177,56.577 J2.A26
  Bottom Layer w0.381: v4(1.8,10.1) 3,10.1 7.379,5.721 23.861,5.721 25.79,7.65 v4(86.65,7.65)
S2_B: J2.A27 S2_B.K | length 124.1
  Bottom Layer w0.381: v4(1.722,30.794) 3.04,32.112 3.04,41.2 4.04,42.2 30.3,42.2 31.301,41.199 31.301,34.711 33.22,32.792 33.22,32.68 72.62,32.68 73.84,33.9 73.84,44.051 86.512,56.723 87.383,56.723 88.237,57.577 89.221,57.577 90.031,56.767 91.133,56.767 J2.A27 J2.A27@91.22,56.62
S2_R: J2.A28 S2_R.K | length 112
  Bottom Layer w0.381: v4(1.722,29.144) 6.068,29.144 6.825,29.9 17.368,29.9 18.862,28.406 28.694,28.406 29.6,27.5 72.02,27.5 74.9,30.38 74.9,43.257 86.366,54.723 87.512,54.723 88.439,55.65 J2.A28
S3_B: J2.A29 S3_B.K | length 113.3
  Bottom Layer w0.381: v4(1.823,70.835) 3.566,72.577 87.134,72.577 87.151,72.56 88.151,72.56 90.073,70.638 90.073,70 90.496,69.577 91.634,69.577 92.631,68.58 95.277,68.58 95.5,68.357 95.5,56.589 93.561,54.65 J2.A29
S3_R: J2.A30 S3_R.K | length 108.3
  Top Layer w0.381: J2.A30 94.5,54.9 v3(94.5,66.7) v3@94.477,66.723
  Bottom Layer w0.381: v4(1.84,69.16) 1.84,69.06 3.46,67.44 85.229,67.44 86.366,68.577 87.512,68.577 88.469,67.62 91.747,67.62 92.667,66.7 v3(94.5,66.7)
S4_B: J2.A31 S4_B.K | length 140.1
  Bottom Layer w0.381: v4(1.772,90.794) 1.805,90.76 4.122,90.76 7.642,94.279 38.941,94.279 40.721,92.5 72.44,92.5 74.22,94.28 92.358,94.28 95.97,90.668 95.97,54.77 93.85,52.65 J2.A31
S4_R: J2.A32 S4_R.K | length 130.1
  Top Layer w0.381: J2.A32 95.3,53.7 95.3,86.16 94.24,87.22 v4(93.3,87.22)
  Bottom Layer w0.381: v4(1.772,89.144) 1.836,89.144 3.76,87.22 v4(93.3,87.22)
TX0_N: C10.2 J2.B23 | length 61.1
  Top Layer w0.126: C10.2 37.247,44.93 37.128,44.93 37.054,44.856 37.054,44.729 39.444,42.34 67.935,42.34 71.772,46.178 86.28,60.685 86.573,60.685 86.622,60.636 88.736,60.636 J2.B23
TX0_P: C5.2 J2.B24 | length 61.2
  Top Layer w0.126: C5.2 36.634,44.93 36.753,44.93 36.827,44.856 36.827,44.635 39.349,42.112 64.649,42.112 65.092,42.112 cw(c65.092,41.922) 65.282,41.922 65.282,41.871 ccw(c65.472,41.871) 65.662,41.871 65.662,41.922 cw(c65.852,41.922) 66.042,41.922 66.042,41.885 ccw(c66.232,41.885) 66.422,41.885 66.422,41.922 cw(c66.612,41.922) 66.612,42.112 67.22,42.112 68.029,42.112 72,46.083 86.374,60.458 86.479,60.458 86.553,60.384 86.553,59.847 J2.B24
TX1_N: C8.2 J2.B31 | length 100.5
  Top Layer w0.126: C8.2 37.218,4.929 37.098,4.929 37.024,4.856 37.024,4.729 39.974,1.78 79.072,1.78 84.972,7.68 84.972,51.377 86.28,52.685 86.573,52.685 86.622,52.636 88.736,52.636 J2.B31
TX1_P: C3.2 J2.B32 | length 100.5
  Top Layer w0.126: C3.2 36.604,4.929 36.723,4.929 36.797,4.856 36.797,4.635 39.88,1.552 46.32,1.552 46.763,1.552 cw(c46.763,1.362) 46.953,1.362 46.953,1.311 ccw(c47.143,1.311) 47.333,1.311 47.333,1.362 cw(c47.523,1.362) 47.713,1.362 47.713,1.325 ccw(c47.903,1.325) 48.093,1.325 48.093,1.362 cw(c48.283,1.362) 48.283,1.552 49.3,1.552 79.167,1.552 85.2,7.586 85.2,51.283 86.374,52.458 86.479,52.458 86.553,52.384 86.553,51.847 J2.B32
TX2_N: C9.2 J2.B27 | length 78.7
  Top Layer w0.126: C9.2 37.198,24.929 37.078,24.929 37.004,24.856 37.004,24.729 39.155,22.578 71.531,22.578 75.7,26.748 75.7,45.731 86.619,56.65 J2.B27
TX2_P: C4.2 J2.B28 | length 79.4
  Top Layer w0.126: C4.2 36.584,24.929 36.703,24.929 36.777,24.856 36.777,24.635 39.061,22.351 71.625,22.351 75.928,26.653 75.928,36.308 75.928,36.384 75.928,36.751 cw(c76.079,36.751) 76.079,36.903 76.106,36.903 ccw(c76.106,37.055) 76.106,37.207 76.079,37.207 cw(c76.079,37.359) 76.079,37.51 76.106,37.51 ccw(c76.106,37.662) 76.106,37.814 76.079,37.814 cw(c76.079,37.966) 76.079,38.118 76.106,38.118 ccw(c76.106,38.27) 76.106,38.422 76.079,38.422 cw(c76.079,38.574) 76.079,38.726 76.106,38.726 ccw(c76.106,38.878) 76.106,39.029 76.079,39.029 cw(c76.079,39.181) 76.079,39.333 ccw(c76.08,39.485) 76.08,39.637 cw(c76.079,39.789) 75.928,39.789 75.928,40.14 75.928,45.637 86.545,56.254 86.545,55.855 J2.B28
TX3_N: C11.2 J2.B19 | length 54.1
  Top Layer w0.126: C11.2 37.198,64.929 37.078,64.929 37.004,64.856 37.004,64.729 38.895,62.838 66.257,62.838 68.103,64.685 86.573,64.685 86.622,64.636 88.736,64.636 J2.B19
TX3_P: C6.2 J2.B20 | length 54.2
  Top Layer w0.126: C6.2 36.584,64.929 36.703,64.929 36.777,64.856 36.777,64.635 38.801,62.611 66.351,62.611 68.198,64.458 72.68,64.458 73.123,64.458 cw(c73.123,64.268) 73.313,64.268 73.313,64.216 ccw(c73.503,64.216) 73.693,64.216 73.693,64.268 cw(c73.883,64.268) 74.073,64.268 74.073,64.231 ccw(c74.263,64.231) 74.453,64.231 74.453,64.268 cw(c74.643,64.268) 74.643,64.458 76.06,64.458 86.479,64.458 86.553,64.384 86.553,63.847 J2.B20
TX4_N: C12.2 J2.B15 | length 60.4
  Top Layer w0.126: C12.2 37.197,84.93 37.078,84.93 37.004,84.856 37.004,84.729 39.035,82.698 71.822,82.698 75.097,79.423 75.097,77.463 83.875,68.685 86.573,68.685 86.608,68.65 J2.B15
TX4_P: C7.2 J2.B16 | length 60.4
  Top Layer w0.126: C7.2 36.583,84.93 36.703,84.93 36.777,84.856 36.777,84.635 38.941,82.471 71.727,82.471 74.869,79.329 74.869,77.369 75.429,76.809 75.706,76.532 cw(c75.59,76.415) 75.706,76.299 75.652,76.244 ccw(c75.768,76.128) 75.652,76.012 ccw(c75.768,76.128) 75.885,76.012 75.939,76.066 cw(c76.056,75.95) 76.172,76.066 cw(c76.056,75.95) 76.172,75.833 76.125,75.786 ccw(c76.241,75.67) 76.125,75.553 ccw(c76.241,75.67) 76.357,75.553 76.405,75.601 cw(c76.521,75.484) 76.637,75.601 77.299,74.939 83.78,68.458 86.479,68.458 86.553,68.384 86.553,67.847 J2.B16
VCC_3.3V: J1.9 J1.11 J2.A22 | length 97.4
  Top Layer w1.27: J1.9 J1.11 20.744,95.956 21.2,95.956 23.556,93.6 30.544,93.6 31.668,94.724 92.543,94.724 97.64,89.626 v6(97.64,75.32)
VIN: C2.2 F1.2 J1.15 J2.A1 J2.A2 J2.A3 J2.A4 J2.A5 J2.A6 J2.A7 J2.A8 J2.B1 J2.B2 J2.B3 J2.B4 J2.B5 J2.B6 J2.B7 J2.B8 TC1.1 TC2.1 TC3.1 U1.2 | length 25.9
  Top Layer w2.54: U1.2 10.46,27.14 15.703,21.897 v2(16.28,21.897) ; J2.B6 86.75,78.63 86.84,78.54 ; J2.A6 93.25,78.75 93.3,78.7
  Bottom Layer w2.54: 10.04,25.36 10.094,25.414 10.094,25.475 10.46,25.841 U1.2 ; F1.2@16.25,21.867 16.377,21.74 TC2.1@23.86,21.74 ; v2(23.86,21.83) 24.129,21.561 24.991,21.561 25.054,21.498 27.158,21.498 TC3.1@27.4,21.74 ; TC3.1@27.58,21.761 v2(27.58,21.78)
  other v2: 20.23,21.86
pads on no net: D2.1 J2.65 J2.66 J2.A12 J2.A13 J2.A14 S1.0 S1.3 SA0.0 SA0.8 SA0.9 SA0.10 SA0.20 SA0.21 SA0.22 SA1.0 SA1.8 SA1.9 SA1.10 SA1.20 SA1.21 SA1.22 SA2.0 SA2.8 SA2.9 SA2.10 SA2.20 SA2.21 SA2.22 SA3.0 SA3.8 SA3.9 SA3.10 SA3.20 SA3.21 SA3.22 SA4.0 SA4.8 SA4.9 SA4.10 SA4.20 SA4.21 SA4.22 U1.5 U1.7
copper on no net:
  other v1: 3.5,1.3 96.5,1.3 2.658,1.467 4.342,1.467 95.658,1.467 97.342,1.467 1.944,1.944 5.056,1.944 94.944,1.944 98.056,1.944 1.467,2.658 5.533,2.658 94.467,2.658 98.533,2.658 1.3,3.5 5.7,3.5 94.3,3.5 98.7,3.5 1.467,4.342 5.533,4.342 94.467,4.342 98.533,4.342 1.944,5.056 5.056,5.056 94.944,5.056 98.056,5.056 2.658,5.533 4.342,5.533 95.658,5.533 97.342,5.533 3.5,5.7 96.5,5.7 9,6.8 91,6.8 8.158,6.967 9.842,6.967 90.158,6.967 91.842,6.967 7.444,7.444 10.556,7.444 89.444,7.444 92.556,7.444 6.967,8.158 11.033,8.158 88.967,8.158 93.033,8.158 6.8,9 11.2,9 88.8,9 93.2,9 6.967,9.842 11.033,9.842 88.967,9.842 93.033,9.842 7.444,10.556 10.556,10.556 89.444,10.556 92.556,10.556 8.158,11.033 9.842,11.033 90.158,11.033 91.842,11.033 9,11.2 91,11.2 9,88.8 91,88.8 8.158,88.967 9.842,88.967 90.158,88.967 91.842,88.967 7.444,89.444 10.556,89.444 89.444,89.444 92.556,89.444 6.967,90.158 11.033,90.158 88.967,90.158 93.033,90.158 6.8,91 11.2,91 88.8,91 93.2,91 6.967,91.842 11.033,91.842 88.967,91.842 93.033,91.842 7.444,92.556 10.556,92.556 89.444,92.556 92.556,92.556 8.158,93.033 9.842,93.033 90.158,93.033 91.842,93.033 9,93.2 91,93.2 3.5,94.3 96.5,94.3 2.658,94.467 4.342,94.467 95.658,94.467 97.342,94.467 1.944,94.944 5.056,94.944 94.944,94.944 98.056,94.944 1.467,95.658 5.533,95.658 94.467,95.658 98.533,95.658 1.3,96.5 5.7,96.5 94.3,96.5 98.7,96.5 1.467,97.342 5.533,97.342 94.467,97.342 98.533,97.342 1.944,98.056 5.056,98.056 94.944,98.056 98.056,98.056 2.658,98.533 4.342,98.533 95.658,98.533 97.342,98.533 3.5,98.7 96.5,98.7

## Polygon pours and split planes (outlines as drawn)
GND on Bottom Layer "Top Layer-No Net" (hatched 90Degree grid 0.508 track 0.203, remove dead copper, pour order 0): 0,3.5 0,96.5 cw(c3.5,96.5) 3.5,100 96.5,100 cw(c96.5,96.5) 100,96.5 100,3.5 cw(c96.5,3.5) 96.5,0 3.5,0 cw(c3.5,3.5)
GND on Int1 (GND) (split plane): 97.084,99.438 97.463,99.337 97.825,99.187 98.164,98.991 98.475,98.752 98.752,98.475 98.991,98.164 99.187,97.825 99.337,97.463 99.438,97.084 99.49,96.696 99.49,96.5 99.49,3.5 99.49,3.304 99.438,2.916 99.337,2.537 99.187,2.175 98.991,1.836 98.752,1.525 98.475,1.248 98.164,1.009 97.825,0.813 97.463,0.663 97.084,0.562 96.696,0.51 3.304,0.51 2.916,0.562 2.537,0.663 2.175,0.813 1.836,1.009 1.525,1.248 1.248,1.525 1.009,1.836 0.813,2.175 0.663,2.537 0.562,2.916 0.51,3.304 0.51,3.5 0.51,96.5 0.51,96.696 0.562,97.084 0.663,97.463 0.813,97.825 1.009,98.164 1.248,98.475 1.525,98.752 1.836,98.991 2.175,99.187 2.537,99.337 2.916,99.438 3.304,99.49 96.696,99.49
VIN on Int2 (PWR) (split plane): 489 vertices, not listed, extent 14.285,0.51 99.49,99.49
5.0V on Int2 (PWR) (split plane): 344 vertices, not listed, extent 0.51,0.51 46.078,99.49
5.0V on Int2 (PWR) (split plane): 184 vertices, not listed, extent 54.483,0.51 99.49,92.116
VCC_3.3V on Int2 (PWR) (split plane): 99.49,60.141 90.363,60.104 90.363,70.297 94.54,70.297 94.543,70.297 94.546,70.297 94.58,70.301 94.615,70.305 94.618,70.305 94.62,70.306 94.653,70.316 94.687,70.326 94.689,70.328 94.692,70.329 94.722,70.345 94.753,70.362 94.755,70.364 94.758,70.365 94.784,70.387 94.811,70.409 94.813,70.412 94.815,70.413 94.836,70.441 94.858,70.467 94.86,70.47 94.862,70.472 94.877,70.503 94.894,70.533 94.895,70.536 94.896,70.539 94.905,70.572 94.915,70.605 94.916,70.608 94.917,70.611 94.919,70.646 94.923,70.68 94.923,70.683 94.923,70.686 94.831,76.653 94.832,77.486 99.49,77.514

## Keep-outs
Keep-Out Layer:
  pour cut-out: 32.5,75.5 71.5,75.5 71.5,81.5 32.5,81.5
  lines w0.127: 0,3.5 ccw(c3.5,3.5) 3.5,0 96.5,0 ccw(c96.5,3.5) 100,3.5 100,96.5 ccw(c96.5,96.5) 96.5,100 3.5,100 ccw(c3.5,96.5) 0,96.5 0,3.5
  lines w0.762: 32,15 71,15 71,21 32,21 32,15 ; 32,35 71,35 71,41 32,41 32,35 ; 32,55.5 32,61.5 71,61.5 71,55.5 32,55.5 ; 32.5,75.5 32.5,81.5 71.5,81.5 71.5,75.5 32.5,75.5

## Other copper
Int2 (PWR) (plane layer: these items are gaps in the copper):
  lines w0.762: 13.95,23.35 13.99,26.8 46.461,26.8 46.461,32.548 13.969,32.229 13.902,33.411 13.945,46.478 46.129,46.52 46.206,52.835 18.419,52.872 18.381,67.088 46.461,67.254 46.394,72.86 18.32,73.007 18.32,87.2 46.09,87.2 46.136,92.961 18.537,93.021 18.556,100.018 ; 14,0.04 14.019,6.737 46.38,6.743 46.38,7.589 46.38,13.216 14.135,13.29 14.05,15.812 14.1,23.15 ; 54.1,77 54.14,92.5 74.56,92.44 74.579,77.799 84.054,77.803 100,77.9 ; 54.1,77.2 54.1,76.8 54.1,76.35 54.1,75.1 54.15,0 ; 94.45,77.8 94.448,76.65 94.54,70.68 89.98,70.68 89.98,59.72 100,59.76

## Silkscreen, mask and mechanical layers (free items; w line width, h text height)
Top Overlay:
  text "5" at 82.5,85.41 h15 r90
  text "1" at 26.6,70.672 h30 r90
  text "5" at 82.5,65.41 h15 r90
  text "4" at 19,56.435 h30 r90
  text "5" at 82.5,45.41 h15 r90
  text "5" at 82.5,25.41 h15 r90
  text "5" at 82.5,5.41 h15 r90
